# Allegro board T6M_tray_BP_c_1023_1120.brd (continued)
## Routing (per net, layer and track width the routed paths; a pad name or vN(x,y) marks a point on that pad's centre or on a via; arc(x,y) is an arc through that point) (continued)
ENET1G_3_MDI1N: length 33.3
  IN2 w0.152: J7.F2 347.53,8.64 347.67,8.5 348.18,8.5 348.43,8.76 348.43,19.85 346.93,21.35 346.93,27.7 346.4,28.23 346.4,30.22 347.48,31.3 347.48,33.37 345.98,34.87 344.8,34.87 343.69,35.98 J23.A6
ENET1G_3_MDI1P: length 33.7
  IN2 w0.152: J23.A3 346.45,38.51 346.45,34.98 347.89,33.54 347.89,31.13 346.81,30.05 346.81,28.4 347.34,27.86 347.34,21.51 348.84,20.02 348.84,8.59 348.35,8.1 347.67,8.1 347.53,7.96 J7.E2
ENET1G_3_MDI2N: length 41.8
  BOTTOM w0.147: J7.C2 347.53,4.4 347.38,4.25 346.84,4.25 346.69,4.4 346.69,14.68 350.46,18.46 350.46,21.58 350.62,21.74 350.62,22.18 350.46,22.34 350.46,22.78 350.62,22.94 350.62,23.38 350.46,23.54 350.46,23.98 350.62,24.14 350.62,24.58 350.46,24.74 350.46,25.18 350.62,25.34 350.62,25.78 350.46,25.94 350.46,32.51 348.58,34.39 347.5,34.39 346.61,35.28 346.61,36.8 345.81,37.61 344.82,37.61 344.73,37.52 344.6,37.45 344.4,37.52 J23.A5
ENET1G_3_MDI2P: length 41.1
  BOTTOM w0.147: J23.A4 344.67,36.98 344.74,37.18 344.91,37.27 344.95,37.3 345.68,37.3 346.3,36.68 346.3,35.15 347.37,34.09 348.46,34.09 350.16,32.38 350.16,18.59 346.38,14.81 346.38,4.27 346.71,3.95 347.36,3.95 347.53,3.78 J7.B2
ENET1G_3_MDI3N: length 55.1
  IN1 w0.152: J7.B3 345.53,3.16 345.37,3 345.03,3 344.73,3.3 344.73,14.33 346.71,16.31 346.71,25.66 350.67,29.62 350.67,33.71 350.41,33.96 350.41,39.42 349.65,40.18 340.79,40.18 339.78,39.17 339.78,37.7 340.32,37.16 340.45,37.16 340.5,37.14 340.57,36.93 J23.A8
ENET1G_3_MDI3P: length 54.4
  IN1 w0.152: J7.A3 345.53,2.46 345.39,2.6 344.86,2.6 344.32,3.13 344.32,14.49 346.3,16.48 346.3,17.89 346.15,18.04 346.15,18.5 346.3,18.65 346.3,19.11 346.15,19.26 346.15,19.71 346.3,19.87 346.3,20.32 346.15,20.48 346.15,20.93 346.3,21.09 346.3,21.54 346.15,21.7 346.15,22.15 346.3,22.31 346.3,25.83 350.26,29.79 350.26,33.54 350.01,33.79 350.01,39.25 349.48,39.78 340.96,39.78 340.18,39 340.18,37.87 340.49,37.57 340.54,37.57 340.68,37.5 340.68,37.5 340.88,37.57 J23.A7
ENET1G_4_MDI0N: length 33.3
  IN2 w0.152: J7.C4 343.53,4.44 343.66,4.3 344.18,4.3 344.33,4.46 344.33,15.34 341.5,18.17 341.5,24.28 338.5,27.28 338.5,30.2 339.39,31.09 340.42,31.09 340.54,30.97 340.68,30.9 340.88,30.97 J23.B2
ENET1G_4_MDI0P: length 33.1
  IN2 w0.152: J23.B1 340.57,30.33 340.5,30.54 340.3,30.63 340.26,30.68 339.55,30.68 338.91,30.03 338.91,27.45 341.91,24.45 341.91,18.34 344.74,15.51 344.74,4.29 344.35,3.9 343.66,3.9 343.53,3.77 J7.B4
ENET1G_4_MDI1N: length 35.7
  IN1 w0.152: J7.B5 341.53,3.17 341.69,3 342.07,3 342.26,3.19 342.26,18.8 343.43,19.96 343.43,26.57 341.04,28.96 341.04,30.02 341.8,30.78 345.31,30.78 J23.B6
ENET1G_4_MDI1P: length 35
  IN1 w0.152: J7.A5 341.53,2.4 341.73,2.6 342.24,2.6 342.67,3.02 342.67,18.63 343.83,19.8 343.83,26.74 341.45,29.12 341.45,29.85 341.97,30.38 343.89,30.38 344.09,30.18 344.09,29.64 343.83,29.38 J23.B3
ENET1G_4_MDI2N: length 29.3
  BOTTOM w0.147: J23.B5 344.67,30.38 344.74,30.58 344.91,30.67 345,30.76 345.67,30.76 346.1,30.33 346.1,27.2 345.72,26.83 345.49,26.83 345.18,26.51 345.18,26.28 344.87,25.97 344.64,25.97 344.33,25.66 344.33,25.43 344.02,25.12 343.79,25.12 343.47,24.81 343.47,24.58 342.49,23.59 342.49,7.42 342.23,7.15 341.63,7.15 341.53,7.25 J7.E5
ENET1G_4_MDI2P: length 30
  BOTTOM w0.147: J7.D5 341.53,6.72 341.66,6.85 342.35,6.85 342.79,7.29 342.79,23.46 346.41,27.08 346.41,30.45 345.8,31.06 344.88,31.06 344.73,30.92 344.6,30.85 344.4,30.92 J23.B4
ENET1G_4_MDI3N: length 44.4
  IN1 w0.152: J23.B8 348.5,30.97 348.3,30.9 348.16,30.97 347.9,31.23 347.9,32.79 346.68,34.01 340.71,34.01 338.65,31.95 338.65,27.59 341.6,24.64 341.6,20.97 340.33,19.7 340.33,4.64 339.99,4.3 339.69,4.3 339.53,4.47 J7.C6
ENET1G_4_MDI3P: length 44.2
  IN1 w0.152: J23.B7 348.19,30.33 348.12,30.54 347.92,30.63 347.49,31.06 347.49,32.62 346.51,33.6 340.88,33.6 339.06,31.78 339.06,27.76 342.01,24.81 342.01,20.8 340.74,19.53 340.74,4.47 340.16,3.9 339.69,3.9 339.53,3.73 J7.B6
ENET10G_1_LOS: length 13.5
  TOP w0.29: U5.8 v1(140.29,19.94) ; R13.2 130.5,22.78 130.55,22.73 R67.1 v1(131.19,22.21)
  IN2 w0.183: v1(140.29,19.94) 139.96,19.61 138.02,19.61 136.12,21.51 131.89,21.51 v1(131.19,22.21)
ENET10G_1_MOD_DEF0: length 18
  TOP w0.29: R66.1 131.02,21.14 132.19,22.31 v1(132.19,23.11) 130.96,24.35 R9.2 ; U5.6 v1(141.89,20.12)
  IN2 w0.183: v1(141.89,20.12) 141.12,20.12 140.79,20.45 139.04,20.45 135.97,23.52 134.16,23.52 133.76,23.11 v1(132.19,23.11)
ENET10G_1_RDN: length 20
  TOP w0.244: v1(132.92,5.23) 133.1,5.04 arc(133.27,4.93) 133.46,4.89 133.74,4.89 arc(133.93,4.93) 134.1,5.04 134.14,5.08 arc(134.31,5.19) 134.5,5.23 134.76,5.23 arc(134.89,5.21) 134.99,5.14 135.09,5.04 arc(135.26,4.93) 135.45,4.89 135.68,4.89 arc(135.87,4.93) 136.04,5.04 136.08,5.08 arc(136.25,5.19) 136.44,5.23 136.68,5.23 arc(136.81,5.21) 136.92,5.14 137.01,5.04 arc(137.18,4.93) 137.37,4.89 137.75,4.89 arc(137.95,4.93) 138.11,5.04 138.15,5.08 arc(138.32,5.19) 138.51,5.23 138.72,5.23 arc(138.87,5.2) 139,5.12 139.12,5 arc(139.24,4.92) 139.38,4.89 139.53,4.89 arc(139.62,4.91) 139.7,4.96 139.92,5.18 arc(139.97,5.26) 139.99,5.35 139.99,5.79 arc(139.95,5.98) 139.84,6.15 139.81,6.18 arc(139.7,6.35) 139.66,6.54 139.66,6.8 arc(139.7,6.99) 139.81,7.16 139.99,7.34 139.99,8.85 139.89,8.95 139.89,8.95 U5.12
  BOTTOM w0.244: J24.E1 128.93,7.3 129.33,7.3 arc(129.64,7.24) 129.9,7.06 arc(130.08,6.8) 130.14,6.49 130.14,5.23 arc(130.17,5.1) 130.24,4.99 arc(130.35,4.92) 130.48,4.89 arc(130.61,4.92) 130.72,4.99 130.81,5.08 arc(130.97,5.19) 131.15,5.22 131.35,5.22 arc(131.54,5.18) 131.71,5.07 131.74,5.04 arc(131.9,4.93) 132.1,4.89 132.37,4.89 arc(132.57,4.93) 132.73,5.04 v1(132.92,5.23)
ENET10G_1_RDP: length 20
  TOP w0.244: v1(132.92,3.96) 133.25,4.29 139.67,4.29 arc(139.86,4.33) 140.03,4.44 140.44,4.86 arc(140.55,5.02) 140.59,5.21 140.59,8.85 140.69,8.95 U5.13
  BOTTOM w0.244: v1(132.92,3.96) 132.58,4.29 130.48,4.29 arc(130.12,4.36) 129.81,4.57 arc(129.61,4.87) 129.54,5.23 129.54,6.49 arc(129.52,6.57) 129.48,6.64 arc(129.41,6.68) 129.33,6.7 128.93,6.7 J24.D1
ENET10G_1_RS0: length 21.2
  TOP w0.29: R11.2 v1(156.34,25.44) R42.2 ; v1(143.21,22.28) 141.09,20.16 U5.7
  IN2 w0.183: v1(143.21,22.28) 146.3,22.28 147.57,23.55 150.77,23.55 152.67,25.44 v1(156.34,25.44)
ENET10G_1_RS1: length 24.8
  TOP w0.29: R15.2 v1(156.34,26.71) R43.2 ; U5.9 v1(139.49,22.71)
  IN2 w0.183: v1(139.49,22.71) 140.49,22.71 140.67,22.89 146.05,22.89 147.24,24.08 150.55,24.08 153.18,26.71 v1(156.34,26.71)
ENET10G_1_SCL: length 36.2
  TOP w0.29: v1(131.93,24.49) 130.97,25.44 R7.2 ; U5.5 v1(142.69,20.52)
  IN1 w0.183: v1(131.93,24.49) 131.8,24.49 127.64,20.32 127.64,16.55 125.22,14.14 125.22,8.39 J24.E3
  IN2 w0.183: v1(131.93,24.49) 132.23,24.18 136.27,24.18 139.3,21.15 142.07,21.15 v1(142.69,20.52)
ENET10G_1_SDA: length 41.7
  TOP w0.29: v1(133.53,25.22) 132.22,26.53 R5.2 ; U5.4 v1(143.49,20.8)
  IN1 w0.183: v1(133.53,25.22) 133.53,24.87 132.38,23.72 132.03,23.72 128.32,20.02 128.32,16.1 127.58,15.37 127.58,7.39 127.08,6.88 125.11,6.88 J24.D3
  IN2 w0.183: v1(143.49,20.8) 142.27,22.02 139.38,22.02 136.18,25.22 v1(133.53,25.22)
ENET10G_1_TDN: length 25.6
  TOP w0.244: U5.19 145.49,8.95 145.39,8.85 145.39,6.05 v1(145.73,5.71)
  BOTTOM w0.244: v1(145.73,5.71) 145.39,6.05 145.39,6.72 arc(145.35,6.92) 145.24,7.08 144.98,7.34 arc(144.81,7.45) 144.62,7.49 143.98,7.49 arc(143.56,7.41) 143.2,7.17 142.76,6.73 arc(142.6,6.62) 142.4,6.58 135.63,6.58 arc(135.53,6.6) 135.45,6.65 130.93,11.18 arc(130.57,11.42) 130.14,11.5 128.93,11.5 J24.H1
ENET10G_1_TDP: length 25.6
  TOP w0.244: v1(144.46,5.71) 144.79,6.05 144.79,8.85 144.69,8.95 U5.18
  BOTTOM w0.244: v1(144.46,5.71) 144.79,6.05 144.79,6.58 arc(144.77,6.68) 144.72,6.76 144.65,6.82 arc(144.57,6.88) 144.48,6.89 143.98,6.89 arc(143.79,6.85) 143.63,6.74 143.18,6.3 arc(142.82,6.06) 142.4,5.98 141.98,5.98 arc(141.82,5.95) 141.68,5.87 arc(141.67,5.86) 141.66,5.85 arc(141.51,5.75) 141.34,5.71 140.95,5.71 arc(140.78,5.75) 140.63,5.85 arc(140.62,5.86) 140.61,5.87 arc(140.48,5.95) 140.32,5.98 139.87,5.98 arc(139.71,5.95) 139.57,5.87 arc(139.56,5.86) 139.55,5.85 arc(139.41,5.75) 139.23,5.71 138.85,5.71 arc(138.67,5.75) 138.53,5.85 arc(138.52,5.86) 138.51,5.87 arc(138.37,5.95) 138.21,5.98 137.79,5.98 arc(137.63,5.95) 137.49,5.87 arc(137.48,5.86) 137.47,5.85 arc(137.32,5.75) 137.15,5.71 136.79,5.71 arc(136.62,5.75) 136.47,5.85 arc(136.47,5.85) 136.46,5.85 136.45,5.87 arc(136.31,5.95) 136.15,5.98 135.49,5.98 arc(135.29,6.02) 135.13,6.13 134.95,6.31 arc(134.78,6.42) 134.59,6.45 134.55,6.45 arc(134.36,6.49) 134.19,6.6 133.97,6.82 arc(133.86,6.99) 133.83,7.18 133.83,7.22 arc(133.79,7.41) 133.68,7.58 133.46,7.8 arc(133.29,7.91) 133.1,7.95 133.04,7.95 arc(132.84,7.98) 132.68,8.09 132.48,8.29 arc(132.37,8.45) 132.33,8.65 132.33,8.71 arc(132.3,8.9) 132.19,9.07 131.97,9.29 arc(131.8,9.4) 131.61,9.44 131.6,9.44 arc(131.4,9.48) 131.24,9.59 130.99,9.83 arc(130.88,10) 130.84,10.19 130.84,10.2 arc(130.8,10.4) 130.69,10.56 130.5,10.75 arc(130.34,10.86) 130.14,10.9 128.93,10.9 J24.G1
ENET10G_1_TX_DIS: length 17.8
  TOP w0.29: U5.3 v1(144.29,20.7) ; R3.2 v1(156.36,24.17) R41.2
  IN2 w0.183: v1(156.36,24.17) 154.16,24.17 151.45,21.46 145.05,21.46 v1(144.29,20.7)
ENET10G_1_TX_FAULT: length 16
  TOP w0.29: U5.2 v1(145.09,20.24) ; R1.2 v1(156.18,22.9) R40.2
  IN2 w0.183: v1(145.09,20.24) 145.8,20.95 151.66,20.95 153.61,22.9 v1(156.18,22.9)
ENET10G_2_LOS: length 26.2
  TOP w0.29: v1(114.81,25.96) 114.81,25.98 115.37,26.55 R14.2 ; R68.1 v1(118.41,22.24) ; U6.8 v1(102.37,22.74)
  IN2 w0.183: v1(118.41,22.24) 115.57,25.08 115.57,25.2 v1(114.81,25.96) 114.25,25.96 112.48,24.19 103.81,24.19 v1(102.37,22.74)
ENET10G_2_MOD_DEF0: length 24
  TOP w0.29: R69.1 v1(118.39,21.15) ; v1(114.83,24.64) 115.65,25.45 R10.2 ; U6.6 v1(103.97,22.5)
  IN2 w0.183: v1(118.39,21.15) 118.39,21.41 115.16,24.64 v1(114.83,24.64) 113.67,24.64 112.73,23.7 105.16,23.7 v1(103.97,22.5)
ENET10G_2_RDN: length 23.8
  TOP w0.244: v1(101.73,5.58) 102.07,5.91 102.07,8.85 101.97,8.95 U6.12
  BOTTOM w0.244: J24.F6 118.13,8.6 117.58,8.6 arc(117.16,8.52) 116.8,8.28 115.71,7.18 arc(115.63,7.13) 115.54,7.11 104.32,7.11 arc(104.13,7.15) 103.97,7.26 103.91,7.32 arc(103.74,7.43) 103.55,7.47 102.88,7.47 arc(102.68,7.43) 102.52,7.32 102.14,6.94 arc(102.03,6.78) 101.99,6.58 101.99,5.84 v1(101.73,5.58)
ENET10G_2_RDP: length 23.8
  TOP w0.244: v1(103,5.58) 102.67,5.91 102.67,8.85 102.77,8.95 U6.13
  BOTTOM w0.244: J24.E6 118.13,8 117.58,8 arc(117.39,7.96) 117.22,7.85 116.03,6.66 arc(115.87,6.55) 115.67,6.51 114.57,6.51 arc(114.38,6.47) 114.21,6.36 114.19,6.35 arc(114.03,6.24) 113.84,6.2 113.4,6.2 arc(113.29,6.22) 113.2,6.28 113.12,6.36 arc(112.95,6.47) 112.76,6.51 112.49,6.51 arc(112.3,6.47) 112.14,6.36 112.12,6.35 arc(111.95,6.24) 111.76,6.2 111.34,6.2 arc(111.24,6.22) 111.14,6.28 111.06,6.36 arc(110.9,6.47) 110.7,6.51 110.45,6.51 arc(110.26,6.47) 110.09,6.36 110.08,6.35 arc(109.91,6.24) 109.72,6.2 109.24,6.2 arc(109.13,6.22) 109.04,6.28 108.95,6.36 arc(108.79,6.47) 108.59,6.51 108.41,6.51 arc(108.22,6.47) 108.05,6.36 108.03,6.35 arc(107.87,6.24) 107.67,6.2 107.25,6.2 arc(107.15,6.22) 107.05,6.28 106.97,6.36 arc(106.81,6.47) 106.61,6.51 106.37,6.51 arc(106.17,6.47) 106.01,6.36 arc(105.85,6.26) 105.67,6.22 105.2,6.22 arc(105.11,6.24) 105.03,6.29 104.96,6.36 arc(104.8,6.47) 104.61,6.51 104.32,6.51 arc(103.9,6.6) 103.54,6.84 103.51,6.87 103.02,6.87 arc(102.92,6.85) 102.84,6.8 102.66,6.62 arc(102.61,6.54) 102.59,6.45 102.59,5.99 v1(103,5.58)
ENET10G_2_RS0: length 19.5
  TOP w0.29: U6.7 v1(103.17,20.9) ; R44.2 v1(90.83,27.57) R12.2
  IN2 w0.183: v1(90.83,27.57) 94.83,27.57 101.5,20.9 v1(103.17,20.9)
ENET10G_2_RS1: length 17
  TOP w0.29: R16.2 v1(90.64,26.15) R45.2 ; U6.9 v1(101.57,20.15)
  IN2 w0.183: v1(90.64,26.15) 95.56,26.15 v1(101.57,20.15)
ENET10G_2_SCL: length 35.1
  TOP w0.29: U6.5 v1(104.77,20.55) ; v1(115.29,23.44) 116.21,24.36 R8.2
  IN2 w0.183: v1(104.77,20.55) 104.77,20.8 105.84,21.87 109.51,21.87 109.92,21.46 112.85,21.46 114.83,23.44 v1(115.29,23.44) 117.17,21.56 117.17,12.04 118.11,11.1 118.97,11.1 119.2,10.87 119.21,10.87 120.3,9.78 121.75,9.78 J24.F4
ENET10G_2_SDA: length 33.8
  TOP w0.29: v1(115.14,22.05) 116.36,23.27 R6.2 ; U6.4 v1(105.57,20.5)
  IN2 w0.183: v1(105.57,20.5) 106.1,21.03 109.42,21.03 109.86,20.6 113.08,20.6 114.53,22.05 v1(115.14,22.05) 116.31,20.88 116.31,11.46 118.06,9.7 118.92,9.7 120.24,8.38 121.75,8.38 J24.E4
ENET10G_2_TDN: length 24.3
  TOP w0.244: v1(113.76,9.19) 114.17,8.78 114.17,8.06 arc(114.13,7.86) 114.02,7.7 113.97,7.64 arc(113.86,7.48) 113.82,7.28 113.82,7.02 arc(113.86,6.82) 113.97,6.66 114.02,6.6 arc(114.13,6.44) 114.17,6.24 114.17,5.52 arc(114.15,5.43) 114.1,5.35 113.95,5.19 arc(113.87,5.14) 113.77,5.12 112.72,5.12 arc(112.52,5.16) 112.36,5.27 112.3,5.33 arc(112.14,5.44) 111.94,5.48 111.63,5.48 arc(111.44,5.44) 111.27,5.33 111.21,5.27 arc(111.05,5.16) 110.85,5.12 110.56,5.12 arc(110.36,5.16) 110.2,5.27 110.14,5.33 arc(109.98,5.44) 109.78,5.48 109.45,5.48 arc(109.25,5.44) 109.09,5.33 109.03,5.27 arc(108.86,5.16) 108.67,5.12 108.2,5.12 arc(108,5.16) 107.84,5.27 107.62,5.49 arc(107.51,5.65) 107.47,5.85 107.47,8.85 107.57,8.95 U6.19
  BOTTOM w0.244: J24.I6 118.13,12.8 117.59,12.8 arc(117.39,12.84) 117.23,12.95 117.13,13.04 arc(117.03,13.11) 116.91,13.13 116.47,13.13 arc(116.27,13.09) 116.11,12.98 116.07,12.95 arc(115.91,12.84) 115.71,12.8 115.51,12.8 arc(115.09,12.72) 114.73,12.48 114.5,12.25 arc(114.26,11.89) 114.17,11.46 114.17,11.31 arc(114.14,11.16) 114.06,11.04 114.03,11.01 arc(113.93,10.86) 113.89,10.67 113.89,10.4 arc(113.93,10.2) 114.04,10.04 114.07,10.01 arc(114.14,9.9) 114.17,9.78 114.17,9.61 v1(113.76,9.19)
ENET10G_2_TDP: length 24.3
  TOP w0.244: v1(115.18,9.19) 114.77,8.78 114.77,5.38 arc(114.73,5.19) 114.62,5.02 114.27,4.67 arc(114.11,4.56) 113.91,4.52 108.2,4.52 arc(107.77,4.61) 107.41,4.85 107.19,5.06 arc(106.95,5.42) 106.87,5.85 106.87,8.85 106.77,8.95 U6.18
  BOTTOM w0.244: J24.H6 118.13,12.2 115.51,12.2 arc(115.31,12.16) 115.15,12.05 114.92,11.82 arc(114.81,11.66) 114.77,11.46 114.77,9.61 v1(115.18,9.19)
ENET10G_2_TX_DIS: length 23.2
  TOP w0.29: v1(104.72,21.74) 105.38,21.74 106.37,20.75 U6.3 ; R47.2 v1(90.88,29.12) R4.2
  IN2 w0.183: v1(90.88,29.12) 93.97,29.12 101.35,21.74 v1(104.72,21.74)
ENET10G_2_TX_FAULT: length 13.2
  TOP w0.29: R2.2 R46.2 114.99,21.09 v1(114.58,20.68) ; U6.2 v1(107.17,19.91)
  IN2 w0.183: v1(114.58,20.68) 113.84,19.94 109.42,19.94 109.05,20.31 107.31,20.31 107.17,20.17 v1(107.17,19.91)
ENET10G_3_LOS: length 13.2
  TOP w0.29: R29.2 R70.1 v1(352.4,22.16) ; U7.8 v1(361.29,19.91)
  IN2 w0.183: v1(352.4,22.16) 353.12,21.44 358.62,21.44 359.67,20.39 360.08,20.39 360.55,19.91 v1(361.29,19.91)
ENET10G_3_MOD_DEF0: length 18.1
  TOP w0.29: R25.2 351.81,24.15 352.64,24.15 v1(353.31,23.47) 353.31,22.2 352.21,21.09 R75.1 ; U7.6 v1(362.89,20.07)
  IN2 w0.183: v1(362.89,20.07) 362.23,20.07 361.24,21.06 359.77,21.06 357.36,23.47 v1(353.31,23.47)
ENET10G_3_RDN: length 20
  TOP w0.244: U7.12 360.89,8.95 360.89,8.95 360.99,8.85 360.99,7.34 360.81,7.16 arc(360.7,6.99) 360.66,6.8 360.66,6.54 arc(360.7,6.35) 360.81,6.18 360.84,6.15 arc(360.95,5.98) 360.99,5.79 360.99,5.35 arc(360.97,5.26) 360.92,5.18 360.7,4.96 arc(360.62,4.91) 360.53,4.89 360.38,4.89 arc(360.24,4.92) 360.12,5 360,5.12 arc(359.87,5.2) 359.72,5.23 359.51,5.23 arc(359.32,5.19) 359.15,5.08 359.11,5.04 arc(358.95,4.93) 358.75,4.89 358.37,4.89 arc(358.18,4.93) 358.01,5.04 357.92,5.14 arc(357.81,5.21) 357.68,5.23 357.44,5.23 arc(357.25,5.19) 357.08,5.08 357.04,5.04 arc(356.87,4.93) 356.68,4.89 356.45,4.89 arc(356.26,4.93) 356.09,5.04 355.99,5.14 arc(355.89,5.21) 355.76,5.23 355.5,5.23 arc(355.31,5.19) 355.14,5.08 355.1,5.04 arc(354.93,4.93) 354.74,4.89 354.46,4.89 arc(354.27,4.93) 354.1,5.04 v1(353.92,5.23)
  BOTTOM w0.244: J7.E1 349.93,7.3 350.33,7.3 arc(350.64,7.24) 350.9,7.06 arc(351.08,6.8) 351.14,6.49 351.14,5.23 arc(351.17,5.1) 351.24,4.99 arc(351.35,4.92) 351.48,4.89 arc(351.61,4.92) 351.72,4.99 351.81,5.08 arc(351.97,5.19) 352.15,5.22 352.35,5.22 arc(352.54,5.18) 352.71,5.07 352.74,5.04 arc(352.9,4.93) 353.1,4.89 353.37,4.89 arc(353.57,4.93) 353.73,5.04 v1(353.92,5.23)
ENET10G_3_RDP: length 20
  TOP w0.244: v1(353.92,3.96) 354.25,4.29 360.67,4.29 arc(360.86,4.33) 361.03,4.44 361.44,4.86 arc(361.55,5.02) 361.59,5.21 361.59,8.85 361.69,8.95 U7.13
  BOTTOM w0.244: v1(353.92,3.96) 353.58,4.29 351.48,4.29 arc(351.12,4.36) 350.81,4.57 arc(350.61,4.87) 350.54,5.23 350.54,6.49 arc(350.52,6.57) 350.48,6.64 arc(350.41,6.68) 350.33,6.7 349.93,6.7 J7.D1
ENET10G_3_RS0: length 21.1
  TOP w0.29: v1(364.29,22.38) 362.09,20.18 U7.7 ; R27.2 v1(377.16,26.23) R48.2
  IN2 w0.183: v1(377.16,26.23) 375.32,26.23 373.05,23.95 368.35,23.95 366.78,22.38 v1(364.29,22.38)
ENET10G_3_RS1: length 23.2
  TOP w0.29: v1(363.07,22.48) 363.02,22.48 360.49,19.95 U7.9 ; R49.2 v1(377.14,27.78) R31.2
  IN2 w0.183: v1(363.07,22.48) 363.55,22.96 366.55,22.96 371.36,27.78 v1(377.14,27.78)
ENET10G_3_SCL: length 36.4
  TOP w0.29: U7.5 v1(363.69,20.37) ; v1(353.03,24.79) 352.38,25.44 R23.2
  IN1 w0.183: v1(353.03,24.79) 352.86,24.79 348.08,20.02 348.08,15.77 346.23,13.92 346.23,8.4 J7.E3
  IN2 w0.183: v1(353.03,24.79) 353.62,24.21 357.53,24.21 359.99,21.74 361.85,21.74 362.48,21.11 362.95,21.11 v1(363.69,20.37)
ENET10G_3_SDA: length 41.4
  TOP w0.29: v1(354.38,25.27) 353.12,26.53 R21.2 ; U7.4 v1(364.49,20.75)
  IN1 w0.183: J7.D3 346.14,6.91 347.93,6.91 348.56,7.54 348.56,14.35 348.73,14.52 348.73,19.62 353.16,24.05 353.52,24.05 354.38,24.92 v1(354.38,25.27)
  IN2 w0.183: v1(354.38,25.27) 354.79,24.87 357.78,24.87 360.22,22.43 362.1,22.43 362.72,21.81 363.43,21.81 v1(364.49,20.75)
ENET10G_3_TDN: length 25.6
  TOP w0.244: v1(366.73,5.71) 366.39,6.05 366.39,8.85 366.49,8.95 U7.19
  BOTTOM w0.244: J7.H1 349.93,11.5 351.14,11.5 arc(351.57,11.42) 351.93,11.18 356.45,6.65 arc(356.53,6.6) 356.63,6.58 363.4,6.58 arc(363.6,6.62) 363.76,6.73 364.2,7.17 arc(364.56,7.41) 364.98,7.49 365.62,7.49 arc(365.81,7.45) 365.98,7.34 366.24,7.08 arc(366.35,6.92) 366.39,6.72 366.39,6.05 v1(366.73,5.71)
ENET10G_3_TDP: length 25.6
  TOP w0.244: v1(365.46,5.71) 365.79,6.05 365.79,8.85 365.69,8.95 U7.18
  BOTTOM w0.244: v1(365.46,5.71) 365.79,6.05 365.79,6.58 arc(365.77,6.68) 365.72,6.76 365.65,6.82 arc(365.57,6.88) 365.48,6.89 364.98,6.89 arc(364.79,6.85) 364.63,6.74 364.18,6.3 arc(363.82,6.06) 363.4,5.98 362.98,5.98 arc(362.82,5.95) 362.68,5.87 arc(362.67,5.86) 362.66,5.85 arc(362.51,5.75) 362.34,5.71 361.95,5.71 arc(361.78,5.75) 361.63,5.85 arc(361.63,5.86) 361.61,5.87 arc(361.48,5.95) 361.32,5.98 360.87,5.98 arc(360.71,5.95) 360.57,5.87 arc(360.56,5.86) 360.55,5.85 arc(360.41,5.75) 360.23,5.71 359.85,5.71 arc(359.67,5.75) 359.53,5.85 arc(359.52,5.86) 359.51,5.87 arc(359.37,5.95) 359.21,5.98 358.79,5.98 arc(358.63,5.95) 358.49,5.87 arc(358.48,5.86) 358.47,5.85 arc(358.32,5.75) 358.15,5.71 357.79,5.71 arc(357.62,5.75) 357.47,5.85 arc(357.47,5.85) 357.46,5.85 357.45,5.87 arc(357.31,5.95) 357.15,5.98 356.49,5.98 arc(356.29,6.02) 356.13,6.13 355.95,6.31 arc(355.78,6.42) 355.59,6.45 355.55,6.45 arc(355.36,6.49) 355.19,6.6 354.97,6.82 arc(354.86,6.99) 354.83,7.18 354.83,7.22 arc(354.79,7.41) 354.68,7.58 354.46,7.8 arc(354.29,7.91) 354.1,7.95 354.04,7.95 arc(353.84,7.98) 353.68,8.09 353.48,8.29 arc(353.37,8.45) 353.33,8.65 353.33,8.71 arc(353.3,8.9) 353.19,9.07 352.97,9.29 arc(352.8,9.4) 352.61,9.44 352.6,9.44 arc(352.4,9.48) 352.24,9.59 351.99,9.83 arc(351.88,10) 351.84,10.19 351.84,10.2 arc(351.8,10.4) 351.69,10.56 351.5,10.75 arc(351.34,10.86) 351.14,10.9 349.93,10.9 J7.G1
ENET10G_3_TX_DIS: length 17.6
  TOP w0.29: U7.3 v1(365.29,20.6) ; R51.2 v1(377.19,24.91) R19.2
  IN2 w0.183: v1(377.19,24.91) 374.92,24.91 371.5,21.49 366.18,21.49 v1(365.29,20.6)
ENET10G_3_TX_FAULT: length 15.9
  TOP w0.29: R17.2 v1(377.11,23.64) R50.2 ; U7.2 v1(366.09,20.09)
  IN2 w0.183: v1(366.09,20.09) 366.85,20.85 372.21,20.85 374.99,23.64 v1(377.11,23.64)
ENET10G_4_LOS: length 26.5
  TOP w0.29: v1(338.68,21.06) 338.68,21.06 R72.1 ; U8.8 v1(323.37,22.63) ; R30.2 v1(336.04,25.21)
  IN2 w0.183: v1(338.68,21.06) 338.71,21.08 338.71,21.64 336.04,24.31 v1(336.04,25.21) 335.04,25.21 333.93,24.1 326.24,24.1 324.76,22.63 v1(323.37,22.63)
ENET10G_4_MOD_DEF0: length 23.5
  TOP w0.29: U8.6 v1(324.97,22.15) ; v1(335.64,23.57) 336.1,24.04 R26.2 ; v1(337.69,20.68) 337.95,20.42 339.14,20.42 R73.1
  IN2 w0.183: v1(337.69,20.68) 337.69,21.51 v1(335.64,23.57) 326.39,23.57 v1(324.97,22.15)
ENET10G_4_RDN: length 23.8
  TOP w0.244: U8.12 322.97,8.95 323.07,8.85 323.07,5.91 v1(322.73,5.58)
  BOTTOM w0.244: v1(322.73,5.58) 322.99,5.84 322.99,6.58 arc(323.03,6.78) 323.14,6.94 323.52,7.32 arc(323.68,7.43) 323.88,7.47 324.55,7.47 arc(324.74,7.43) 324.91,7.32 324.97,7.26 arc(325.13,7.15) 325.32,7.11 336.54,7.11 arc(336.63,7.13) 336.71,7.18 337.8,8.28 arc(338.16,8.52) 338.58,8.6 339.13,8.6 J7.F6
ENET10G_4_RDP: length 23.8
  TOP w0.244: U8.13 323.77,8.95 323.67,8.85 323.67,5.91 v1(324,5.58)
  BOTTOM w0.244: J7.E6 339.13,8 338.58,8 arc(338.39,7.96) 338.22,7.85 337.03,6.66 arc(336.87,6.55) 336.67,6.51 335.57,6.51 arc(335.38,6.47) 335.21,6.36 335.19,6.35 arc(335.03,6.24) 334.84,6.2 334.4,6.2 arc(334.29,6.22) 334.2,6.28 334.12,6.36 arc(333.95,6.47) 333.76,6.51 333.49,6.51 arc(333.3,6.47) 333.14,6.36 333.12,6.35 arc(332.95,6.24) 332.76,6.2 332.34,6.2 arc(332.24,6.22) 332.14,6.28 332.06,6.36 arc(331.9,6.47) 331.7,6.51 331.45,6.51 arc(331.26,6.47) 331.09,6.36 331.08,6.35 arc(330.91,6.24) 330.72,6.2 330.24,6.2 arc(330.13,6.22) 330.04,6.28 329.95,6.36 arc(329.79,6.47) 329.59,6.51 329.41,6.51 arc(329.22,6.47) 329.05,6.36 329.03,6.35 arc(328.87,6.24) 328.67,6.2 328.25,6.2 arc(328.15,6.22) 328.05,6.28 327.97,6.36 arc(327.81,6.47) 327.61,6.51 327.37,6.51 arc(327.17,6.47) 327.01,6.36 arc(326.85,6.26) 326.67,6.22 326.2,6.22 arc(326.11,6.24) 326.03,6.29 325.96,6.36 arc(325.8,6.47) 325.61,6.51 325.32,6.51 arc(324.9,6.6) 324.54,6.84 324.51,6.87 324.02,6.87 arc(323.92,6.85) 323.84,6.8 323.66,6.62 arc(323.61,6.54) 323.59,6.45 323.59,5.99 v1(324,5.58)
ENET10G_4_RS0: length 19.1
  TOP w0.29: U8.7 v1(324.17,20.07) ; R28.2 v1(311.66,27.52) R52.2
  IN2 w0.183: v1(324.17,20.07) 323.31,20.07 315.85,27.52 v1(311.66,27.52)
ENET10G_4_RS1: length 16.8
  TOP w0.29: R32.2 v1(311.68,26.13) R53.2 ; U8.9 v1(322.57,19.91)
  IN2 w0.183: v1(322.57,19.91) 321.91,20.57 316.36,26.13 v1(311.68,26.13)
ENET10G_4_SCL: length 34.1
  TOP w0.29: v1(335.92,22.3) 336.56,22.95 R24.2 ; U8.5 v1(325.77,21.77)
  IN2 w0.183: J7.F4 342.75,9.78 341.3,9.78 339.97,11.1 339.04,11.1 336.55,13.59 336.55,21.67 v1(335.92,22.3) 334.56,22.3 333.75,21.49 331.47,21.49 330.86,22.1 326.1,22.1 v1(325.77,21.77)
ENET10G_4_SDA: length 33.2
  TOP w0.29: v1(335.66,20.98) 336.32,20.98 337.14,21.8 R22.2 ; U8.4 v1(326.57,21.41)
  IN2 w0.183: v1(326.57,21.41) 330.5,21.41 331.09,20.83 334.47,20.83 334.62,20.98 v1(335.66,20.98) 335.66,12.75 338.73,9.68 339.87,9.68 340.23,9.32 340.23,8.97 340.81,8.38 342.75,8.38 J7.E4
ENET10G_4_TDN: length 24.3
  TOP w0.244: v1(334.76,9.19) 335.17,8.78 335.17,8.06 arc(335.13,7.86) 335.02,7.7 334.97,7.64 arc(334.86,7.48) 334.82,7.28 334.82,7.02 arc(334.86,6.82) 334.97,6.66 335.02,6.6 arc(335.13,6.44) 335.17,6.24 335.17,5.52 arc(335.15,5.43) 335.1,5.35 334.95,5.19 arc(334.87,5.14) 334.77,5.12 333.72,5.12 arc(333.52,5.16) 333.36,5.27 333.3,5.33 arc(333.14,5.44) 332.94,5.48 332.63,5.48 arc(332.44,5.44) 332.27,5.33 332.21,5.27 arc(332.05,5.16) 331.85,5.12 331.56,5.12 arc(331.36,5.16) 331.2,5.27 331.14,5.33 arc(330.98,5.44) 330.78,5.48 330.45,5.48 arc(330.25,5.44) 330.09,5.33 330.03,5.27 arc(329.86,5.16) 329.67,5.12 329.2,5.12 arc(329,5.16) 328.84,5.27 328.62,5.49 arc(328.51,5.65) 328.47,5.85 328.47,8.85 328.57,8.95 U8.19
  BOTTOM w0.244: v1(334.76,9.19) 335.17,9.61 335.17,9.78 arc(335.14,9.9) 335.07,10.01 335.04,10.04 arc(334.93,10.2) 334.89,10.4 334.89,10.67 arc(334.93,10.86) 335.03,11.01 335.06,11.04 arc(335.14,11.16) 335.17,11.31 335.17,11.46 arc(335.26,11.89) 335.5,12.25 335.73,12.48 arc(336.09,12.72) 336.51,12.8 336.71,12.8 arc(336.91,12.84) 337.07,12.95 337.11,12.98 arc(337.27,13.09) 337.47,13.13 337.91,13.13 arc(338.03,13.11) 338.13,13.04 338.23,12.95 arc(338.39,12.84) 338.59,12.8 339.13,12.8 J7.I6
ENET10G_4_TDP: length 24.3
  TOP w0.244: v1(336.18,9.19) 335.77,8.78 335.77,5.38 arc(335.73,5.19) 335.62,5.02 335.27,4.67 arc(335.11,4.56) 334.91,4.52 329.2,4.52 arc(328.77,4.61) 328.41,4.85 328.19,5.06 arc(327.95,5.42) 327.87,5.85 327.87,8.85 327.77,8.95 U8.18
  BOTTOM w0.244: J7.H6 339.13,12.2 336.51,12.2 arc(336.31,12.16) 336.15,12.05 335.92,11.82 arc(335.81,11.66) 335.77,11.46 335.77,9.61 v1(336.18,9.19)
ENET10G_4_TX_DIS: length 22.9
  TOP w0.29: U8.3 v1(327.37,19.91) ; R55.2 v1(311.63,28.97) R20.2
  IN2 w0.183: v1(327.37,19.91) 325.6,19.91 324.26,21.26 322.81,21.26 315.1,28.97 v1(311.63,28.97)
ENET10G_4_TX_FAULT: length 24.5
  TOP w0.29: R18.2 v1(311.63,30.37) R54.2 ; U8.2 v1(328.17,20.37)
  IN2 w0.183: v1(311.63,30.37) 314.39,30.37 322.81,21.95 324.38,21.95 325.6,20.73 327.36,20.73 327.71,20.37 v1(328.17,20.37)
NODE1_EN: length 183.3
  TOP w0.29: J19.S3 6.03,44.26 10.33,39.96 11.66,39.96 14,37.63 16.59,37.63 23.05,31.17 28.69,31.17 v1(29.31,30.55)
  IN1 w0.183: JP4.1 5.21,23.72 14.94,23.72 21.76,30.55 v1(29.31,30.55)
  IN2 w0.183: J24.H2 125.83,12.5 125.83,21.16 125.76,21.23 125.76,24.92 123.23,27.44 123.23,29.93 124.36,31.06 124.36,32.44 122.17,34.62 118.36,34.62 117.63,35.36 113.54,35.36 112.29,34.11 110.79,34.11 109.45,35.46 87,35.46 82.09,30.55 v1(29.31,30.55)
NODE1_RXD: length 156.2
  TOP w0.29: J19.S2 7.3,43.83 10.57,40.56 11.9,40.56 14.24,38.22 16.84,38.22 23.28,31.78 v1(27.28,31.78)
  IN2 w0.183: J24.G3 125.3,11.27 125.3,20.94 125.22,21.01 125.22,24.7 122.69,27.22 122.69,30.14 123.85,31.29 123.85,32.21 121.97,34.09 118.8,34.09 116.2,31.5 112.72,31.5 109.72,34.5 86.91,34.5 82.47,30.06 28.99,30.06 v1(27.28,31.78)
NODE1_TXD: length 152.8
  TOP w0.29: J19.S1 8.57,43.42 10.84,41.15 12.15,41.15 14.49,38.81 17.08,38.81 23.52,32.38 v1(25.17,32.38) ; v1(124.16,18.72) 124.16,17.7 123.65,17.2 123.65,12.78 J24.H3
  IN2 w0.183: v1(124.16,18.72) 124.69,19.25 124.69,24.33 120.73,28.3 120.73,29.79 121.74,30.81 121.74,32.28 120.45,33.58 119.02,33.58 116.41,30.96 112.56,30.96 109.51,34.01 87.11,34.01 82.67,29.57 27.98,29.57 v1(25.17,32.38)
NODE2_EN: length 149.8
  TOP w0.29: v1(33.66,27.97) 33.66,29.09 32.83,29.92 29.01,29.92 28.36,30.57 22.8,30.57 16.42,36.96 13.61,36.96 11.2,39.37 8.94,39.37 4.76,43.55 J19.S4
  IN1 w0.183: v1(33.66,27.97) 32.09,26.41 JP3.1
  IN2 w0.183: v1(33.66,27.97) 83.13,27.97 87.71,32.54 108.92,32.54 119.1,22.36 119.1,14.83 119.84,14.1 119.84,11.19 J24.G5
NODE2_RXD: length 148.7
  TOP w0.29: J19.S6 2.22,43.93 10.44,35.71 15.98,35.71 22.31,29.38 v1(26.06,29.38)
  IN2 w0.183: v1(26.06,29.38) 26.95,28.49 82.97,28.49 87.52,33.04 109.11,33.04 120.02,22.13 120.02,14.86 121.26,13.61 121.26,11.67 J24.G4
NODE2_TXD: length 146.6
  TOP w0.29: J19.S5 3.49,43.58 8.46,38.61 10.83,38.61 13.08,36.36 16.17,36.36 22.56,29.98 27.63,29.98 28.52,29.09 v1(32.66,29.09)
  IN2 w0.183: J24.H4 121.82,12.51 121.82,13.87 120.57,15.11 120.57,22.26 109.31,33.53 87.32,33.53 82.87,29.09 v1(32.66,29.09)
NODE3_EN: length 418.5
  IN1 w0.183: JP8.1 3.71,21.5 3.71,23.88 4.29,24.46 5.69,24.46 5.92,24.23 14.66,24.23 21.54,31.11 27.33,31.11 27.79,31.57 27.79,33.2 28.22,33.63 v1(30.4,33.63)
  IN2 w0.183: v1(30.4,33.63) 81.03,33.63 86.64,39.24 110.42,39.24 113.59,42.41 131.65,42.41 134.9,39.16 203.19,39.16 206.42,35.93 318.09,35.93 322.04,31.98 331.78,31.98 335.25,35.46 337.36,35.46 338.63,34.19 343.66,34.19 345.51,32.33 345.51,31.22 344.23,29.93 344.23,28.47 345.69,27 345.69,20.8 346.83,19.66 346.83,12.5 J7.H2
  BOTTOM w0.29: v1(30.4,33.63) 23.37,33.63 18.57,38.43 13.13,38.43 11.76,39.8 9.45,39.8 6.03,43.22 J19.S10
NODE3_RXD: length 380.6
  IN2 w0.183: J7.G3 346.33,11.3 346.33,19.46 344.7,21.08 344.7,27.15 343.69,28.16 343.69,30.37 344.8,31.47 344.8,32.26 343.4,33.66 339.32,33.66 337.16,31.5 321.82,31.5 317.87,35.44 206.19,35.44 202.96,38.67 134.66,38.67 131.4,41.92 113.79,41.92 110.6,38.73 86.82,38.73 81.21,33.12 30.18,33.12 v1(29.03,34.26)
  BOTTOM w0.29: J19.S11 7.3,43.62 10.53,40.39 12.07,40.39 13.18,39.28 18.81,39.28 23.83,34.26 v1(29.03,34.26)
NODE3_TXD: length 377.2
  TOP w0.29: J7.H3 344.65,12.78 344.65,17.19 v1(344.98,17.53)
  IN2 w0.183: v1(27.66,34.87) 29.92,32.61 81.39,32.61 87,38.23 110.78,38.23 113.99,41.44 131.03,41.44 134.28,38.18 202.73,38.18 205.96,34.96 317.67,34.96 321.61,31.01 337.36,31.01 339.5,33.15 341.87,33.15 342.74,32.28 342.74,30.81 341.73,29.79 341.73,28.3 344.21,25.82 344.21,20.77 345.82,19.15 345.82,18.36 v1(344.98,17.53)
  BOTTOM w0.29: J19.S12 8.57,43.19 10.78,40.99 12.32,40.99 13.43,39.88 19.06,39.88 24.06,34.87 v1(27.66,34.87)
NODE4_EN: length 383.3
  IN1 w0.183: JP7.1 29.24,24.55 29.24,27.1 31.39,29.26 31.39,31.37 29.77,32.99 v1(28.32,32.99)
  IN2 w0.183: J7.G5 340.84,11.19 340.84,14.1 339.24,15.69 339.24,21.89 336.85,24.28 336.85,25.3 332.61,29.55 320.93,29.55 316.98,33.49 205.06,33.49 201.84,36.72 160.32,36.72 159.45,35.84 156.29,35.84 155.41,36.72 133.41,36.72 130.38,39.75 120.27,39.75 117.09,36.58 110.77,36.58 110.16,35.97 86.81,35.97 81.95,31.11 30.21,31.11 v1(28.32,32.99)
  BOTTOM w0.29: J19.S9 4.76,42.99 8.55,39.2 11.52,39.2 12.98,37.74 18.29,37.74 23.04,32.99 v1(28.32,32.99)
NODE4_RXD: length 374.5
  IN2 w0.183: J7.G4 342.26,11.67 342.26,13.61 339.75,16.12 339.75,22.15 337.54,24.36 337.54,25.32 332.83,30.03 321.13,30.03 317.18,33.98 205.33,33.98 202.11,37.21 160.12,37.21 159.26,36.35 156.49,36.35 155.63,37.21 133.68,37.21 130.64,40.24 119.87,40.24 116.71,37.08 87.24,37.08 81.75,31.6 v1(30.43,31.6)
  BOTTOM w0.29: J19.S7 2.22,43.68 9.73,36.17 11.02,36.17 11.38,36.53 17.56,36.53 22.44,31.65 23.87,31.65 24.36,31.17 27.61,31.17 28.04,31.6 v1(30.43,31.6)
NODE4_TXD: length 372.5
  IN2 w0.183: J7.H4 342.82,12.51 342.82,13.87 340.26,16.43 340.26,22.35 338.1,24.51 338.1,25.48 333.05,30.52 321.33,30.52 317.39,34.47 205.63,34.47 202.41,37.69 159.87,37.69 159.03,36.86 156.69,36.86 155.85,37.69 133.98,37.69 130.72,40.95 114.19,40.95 110.89,37.64 87.11,37.64 81.57,32.11 v1(31.75,32.11)
  BOTTOM w0.29: v1(31.75,32.11) 30.76,32.11 30.63,32.23 27.71,32.23 27.56,32.38 26.75,32.38 26.14,31.78 24.59,31.78 24.03,32.33 22.71,32.33 17.92,37.12 12.76,37.12 11.27,38.61 8.15,38.61 3.49,43.27 J19.S8
PS_EN_PSU_N: length 3.3
  TOP w0.29: R33.2 23.56,16.75 J21.1
SAS_BLAD1_RX1_N: length 36
  TOP w0.178: U1.A3 194.49,29.49 194.7,29.7 194.7,30.12 v1(194.26,30.56)
  BOTTOM w0.178: v1(194.26,30.56) 194.72,30.1 194.72,26.9 arc(194.71,26.84) 194.67,26.79 192.89,25.01 arc(192.7,24.73) 192.64,24.4 192.64,22.26 arc(192.63,22.2) 192.59,22.15 177.67,7.22 arc(177.62,7.19) 177.56,7.18 175.41,7.18 J25.E1
SAS_BLAD1_RX1_P: length 37.4
  TOP w0.178: v1(195.53,30.56) 195.05,30.09 195.05,29.74 195.3,29.49 U1.A2
  BOTTOM w0.178: v1(195.53,30.56) 195.07,30.1 195.07,26.9 arc(195.03,26.71) 194.92,26.54 193.14,24.76 arc(193.03,24.6) 192.99,24.4 192.99,22.26 arc(192.95,22.06) 192.84,21.9 189.02,18.08 189.02,17.83 188.64,17.46 188.4,17.46 188.01,17.07 188.01,16.83 187.63,16.45 187.39,16.45 187,16.06 187,15.82 186.63,15.44 186.38,15.44 186,15.05 186,14.81 185.62,14.43 185.37,14.43 184.99,14.04 184.99,13.8 184.61,13.42 184.37,13.42 183.75,12.81 183.75,12.57 183.37,12.19 183.13,12.19 177.92,6.97 arc(177.75,6.86) 177.56,6.82 175.41,6.82 J25.D1
SAS_BLAD1_RX2_N: length 36
  TOP w0.178: v1(191.87,31.68) 192.33,31.22 192.33,29.74 192.09,29.5 U1.A6
  IN2 w0.152: J25.I2 172.89,12.9 172.7,12.7 172.41,12.7 arc(172.27,12.73) 172.15,12.81 arc(172.07,12.93) 172.05,13.07 172.05,13.8 172.08,13.89 173.53,15.34 176.07,16.5 178.17,18.34 180.72,20.44 180.99,20.71 181.21,20.71 181.54,21.03 181.54,21.26 181.86,21.59 182.09,21.59 182.41,21.91 182.41,22.14 182.73,22.46 182.96,22.46 183.29,22.78 183.29,23.01 183.61,23.34 183.84,23.34 184.16,23.66 184.16,23.89 184.48,24.21 184.71,24.21 185.04,24.53 185.04,24.76 185.36,25.09 185.59,25.09 185.91,25.41 185.91,25.64 186.28,26.01 arc(186.35,26.09) 186.39,26.17 187.67,29.25 arc(187.7,29.34) 187.71,29.44 187.71,29.54 arc(187.71,29.57) 187.72,29.59 187.8,29.79 arc(187.82,29.83) 187.84,29.88 188.44,30.77 arc(188.47,30.81) 188.5,30.85 188.93,31.27 arc(188.97,31.31) 189.01,31.34 189.55,31.7 arc(189.59,31.73) 189.64,31.75 191.44,32.5 arc(191.54,32.53) 191.64,32.54 192.12,32.54 arc(192.16,32.53) 192.19,32.51 192.28,32.42 arc(192.3,32.39) 192.31,32.35 192.31,32.11 v1(191.87,31.68)
SAS_BLAD1_RX2_P: length 37.1
  TOP w0.178: U1.A5 192.89,29.5 192.68,29.71 192.68,31.22 v1(193.14,31.68)
  IN2 w0.152: v1(193.14,31.68) 192.71,32.11 192.71,32.35 arc(192.67,32.54) 192.56,32.71 192.48,32.79 arc(192.31,32.91) 192.12,32.94 191.64,32.94 arc(191.46,32.93) 191.29,32.87 189.48,32.12 arc(189.4,32.08) 189.32,32.04 188.78,31.67 arc(188.71,31.62) 188.64,31.56 188.22,31.13 arc(188.16,31.07) 188.1,30.99 187.51,30.1 arc(187.46,30.02) 187.42,29.94 187.34,29.75 arc(187.31,29.64) 187.3,29.54 187.3,29.44 arc(187.3,29.42) 187.29,29.4 186.02,26.33 arc(186.01,26.31) 186,26.3 180.45,20.75 arc(180.44,20.74) 180.44,20.74 177.91,18.65 arc(177.91,18.65) 177.9,18.65 177.9,18.64 175.84,16.84 173.29,15.68 171.74,14.12 171.64,13.89 171.64,13.07 arc(171.7,12.77) 171.87,12.52 arc(172.12,12.36) 172.41,12.3 172.69,12.3 172.89,12.1 J25.H2
SAS_BLAD1_RX3_N: length 37.5
  TOP w0.178: v1(189.46,30.59) 189.92,30.14 189.92,29.73 189.69,29.5 U1.A9
  BOTTOM w0.178: v1(189.46,30.59) 189.92,30.14 189.92,29.17 arc(189.91,29.11) 189.87,29.05 187.58,26.76 arc(187.58,26.76) 187.58,26.76 185.41,24.82 185.41,24.82 181.58,18.8 179.12,17.28 179.11,17.27 arc(179.11,17.27) 179.11,17.27 175.74,14.55 174.66,14.33 arc(174.46,14.29) 174.3,14.18 173.86,13.74 arc(173.75,13.58) 173.72,13.38 173.72,4.53 arc(173.7,4.47) 173.67,4.42 173.57,4.32 arc(173.52,4.29) 173.46,4.28 173.08,4.28 172.89,4.46 J25.C2
SAS_BLAD1_RX3_P: length 38.9
  TOP w0.178: U1.A8 190.49,29.5 190.27,29.73 190.27,30.14 v1(190.73,30.59)
  BOTTOM w0.178: v1(190.73,30.59) 190.27,30.14 190.27,29.17 arc(190.23,28.97) 190.12,28.81 189.73,28.42 189.73,28.17 189.36,27.8 189.11,27.8 188.73,27.41 188.73,27.17 188.35,26.79 188.1,26.79 187.83,26.52 arc(187.82,26.51) 187.81,26.5 185.68,24.59 184.99,23.5 184.98,23.5 185.03,23.26 184.75,22.81 184.51,22.76 184.51,22.75 184.22,22.3 184.22,22.29 184.27,22.06 183.98,21.61 183.75,21.55 183.75,21.55 183.46,21.09 183.45,21.09 183.51,20.85 183.22,20.4 182.98,20.35 182.98,20.34 182.69,19.88 182.69,19.89 182.74,19.65 182.46,19.2 182.22,19.14 182.22,19.14 181.84,18.54 179.32,16.99 175.9,14.23 174.69,13.98 174.66,13.98 arc(174.6,13.96) 174.55,13.93 174.11,13.5 arc(174.08,13.44) 174.07,13.38 174.07,4.53 arc(174.03,4.33) 173.92,4.17 173.82,4.07 arc(173.66,3.96) 173.46,3.92 173.14,3.92 172.89,3.68 J25.B2
SAS_BLAD1_RX4_N: length 36.1
  TOP w0.178: v1(185.5,29.31) 185.04,29.77 185.04,30 185.29,30.25 187.3,30.25 187.54,30.01 187.54,29.75 187.3,29.5 U1.A12
  IN2 w0.152: J25.E3 170.89,7.36 170.74,7.2 170.33,7.2 arc(170.24,7.22) 170.17,7.27 170.14,7.3 arc(170.11,7.35) 170.1,7.4 170.1,13.26 170.22,14.01 170.63,15.01 172.85,17.22 arc(173.02,17.33) 173.21,17.37 173.71,17.37 arc(173.8,17.38) 173.9,17.41 174.48,17.65 arc(174.53,17.67) 174.57,17.7 175.65,18.42 arc(175.69,18.45) 175.73,18.48 178.11,20.87 178.35,20.87 178.68,21.2 178.68,21.43 179,21.76 179.24,21.76 179.56,22.08 179.56,22.32 182.23,24.99 arc(182.43,25.29) 182.5,25.64 182.5,26.33 arc(182.54,26.53) 182.65,26.69 183.65,27.69 arc(183.81,27.8) 184,27.84 184.4,27.84 arc(184.59,27.88) 184.76,27.99 184.92,28.15 arc(185.03,28.31) 185.07,28.51 185.07,28.88 v1(185.5,29.31)
SAS_BLAD1_RX4_P: length 37.7
  TOP w0.178: U1.A11 188.09,29.5 187.9,29.7 187.9,30.15 187.44,30.6 185.15,30.6 184.69,30.14 184.69,29.77 v1(184.23,29.31)
  IN2 w0.152: J25.D3 170.89,6.66 170.76,6.8 170.33,6.8 arc(170.09,6.85) 169.88,6.98 169.86,7.01 arc(169.73,7.19) 169.69,7.4 169.69,13.29 169.83,14.13 170.29,15.24 172.56,17.51 arc(172.86,17.71) 173.21,17.78 173.71,17.78 arc(173.73,17.78) 173.74,17.79 174.33,18.03 arc(174.33,18.03) 174.34,18.04 175.42,18.76 arc(175.43,18.76) 175.44,18.77 181.94,25.28 arc(182.05,25.44) 182.09,25.64 182.09,26.33 arc(182.16,26.68) 182.36,26.98 183.36,27.98 arc(183.65,28.18) 184,28.24 184.4,28.24 arc(184.44,28.25) 184.47,28.27 184.63,28.44 arc(184.65,28.47) 184.66,28.51 184.66,28.88 v1(184.23,29.31)
SAS_BLAD1_RX5_N: length 28.9
  TOP w0.178: v1(175.25,31) 175.71,30.54 175.71,29.73 175.49,29.5 U3.A3
  IN2 w0.152: v1(175.25,31) 175.68,31.43 175.68,31.75 arc(175.67,31.79) 175.65,31.82 175.48,32 arc(175.44,32.02) 175.41,32.03 175.09,32.03 arc(175.05,32.02) 175.02,32 174.78,31.77 174.44,31.42 173.85,30.83 173.84,30.83 arc(173.82,30.79) 173.81,30.75 173.81,29.85 173.99,29.67 173.99,29.26 173.81,29.09 173.81,28.63 173.99,28.45 173.99,28.05 173.81,27.87 173.81,27.28 173.96,27.13 173.96,26.67 173.81,26.52 173.81,26.14 arc(173.85,25.95) 173.96,25.78 174.04,25.7 arc(174.15,25.54) 174.19,25.34 174.19,23.43 arc(174.15,23.23) 174.04,23.07 173.85,22.87 173.85,22.64 173.52,22.32 173.3,22.32 172.97,22 172.97,21.77 172.65,21.44 172.42,21.44 172.1,21.12 172.1,20.89 171.77,20.57 171.55,20.57 170.86,19.88 arc(170.75,19.72) 170.71,19.53 170.71,17.71 arc(170.67,17.52) 170.56,17.35 168.2,14.98 arc(168.09,14.82) 168.05,14.62 168.05,13.09 arc(168.08,12.94) 168.16,12.82 168.16,12.82 arc(168.28,12.73) 168.43,12.7 168.74,12.7 168.89,12.86 J25.I4
SAS_BLAD1_RX5_P: length 30
  TOP w0.178: U3.A2 176.29,29.5 176.06,29.73 176.06,30.54 v1(176.52,31)
  IN2 w0.152: J25.H4 168.89,12.11 168.7,12.3 168.43,12.3 arc(168.13,12.36) 167.87,12.53 arc(167.7,12.79) 167.64,13.09 167.64,14.62 arc(167.71,14.97) 167.91,15.27 170.28,17.64 arc(170.3,17.67) 170.31,17.71 170.31,19.53 arc(170.38,19.88) 170.57,20.17 173.76,23.35 arc(173.78,23.39) 173.79,23.43 173.79,25.34 arc(173.78,25.38) 173.76,25.41 173.67,25.5 arc(173.48,25.79) 173.41,26.14 173.41,30.75 arc(173.45,30.95) 173.56,31.12 174.15,31.71 174.73,32.29 arc(174.89,32.4) 175.09,32.44 175.41,32.44 arc(175.6,32.4) 175.76,32.29 175.94,32.11 arc(176.05,31.95) 176.09,31.75 176.09,31.43 v1(176.52,31)
SAS_BLAD1_RX6_N: length 34.2
  TOP w0.178: v1(172.88,32.92) 173.31,32.48 173.31,29.73 173.08,29.5 U3.A6
  BOTTOM w0.178: v1(172.88,32.92) 173.34,32.46 173.34,27.43 arc(173.4,27.1) 173.59,26.83 173.67,26.74 arc(173.7,26.69) 173.72,26.63 173.72,22.38 arc(173.72,22.37) 173.71,22.36 arc(173.71,22.34) 173.7,22.32 173.44,21.68 arc(173.42,21.65) 173.4,21.63 168.76,16.98 arc(168.73,16.95) 168.72,16.92 168.01,15.2 arc(168,15.19) 168,15.17 167.83,14.46 167.73,14.05 167.72,13.97 167.72,7.37 arc(167.71,7.3) 167.66,7.23 167.66,7.23 arc(167.6,7.19) 167.53,7.18 167.07,7.18 166.89,7.36 J25.E5
SAS_BLAD1_RX6_P: length 35.6
  TOP w0.178: v1(174.15,32.92) 173.66,32.43 173.66,29.73 173.89,29.5 U3.A5
  BOTTOM w0.178: J25.D5 166.89,6.63 167.08,6.82 167.53,6.82 arc(167.74,6.86) 167.91,6.98 167.91,6.98 arc(168.03,7.16) 168.07,7.37 168.07,13.97 168.34,15.08 169.03,16.76 172.71,20.44 172.96,20.44 173.33,20.82 173.33,21.06 173.54,21.26 173.65,21.38 arc(173.72,21.46) 173.76,21.54 174.03,22.18 174.06,22.33 arc(174.07,22.35) 174.07,22.38 174.07,22.49 174.24,22.66 174.24,23.2 174.07,23.37 174.07,23.92 174.24,24.09 174.24,24.62 174.07,24.8 174.07,25.34 174.24,25.52 174.24,26.05 174.07,26.22 174.07,26.63 arc(174.03,26.83) 173.92,26.99 173.83,27.07 arc(173.72,27.24) 173.69,27.43 173.69,27.79 173.86,27.97 173.86,28.5 173.69,28.67 173.69,30.59 173.86,30.76 173.86,31.3 173.69,31.47 173.69,32.46 v1(174.15,32.92)
SAS_BLAD1_RX7_N: length 33.9
  TOP w0.178: U3.A9 170.68,29.5 170.91,29.73 170.91,31.53 v1(170.45,31.99)
  IN2 w0.152: v1(170.45,31.99) 170.88,32.42 170.88,32.77 arc(170.87,32.81) 170.85,32.84 170.73,32.96 arc(170.69,32.99) 170.66,32.99 169.25,32.99 arc(169.05,32.96) 168.89,32.85 166.65,30.6 arc(166.54,30.44) 166.5,30.24 166.5,28.76 arc(166.54,28.57) 166.65,28.4 169.29,25.75 arc(169.4,25.59) 169.44,25.39 169.44,22.74 arc(169.37,22.39) 169.18,22.09 168.95,21.87 168.95,21.74 168.95,21.61 168.63,21.29 168.37,21.29 168.04,20.96 168.04,20.83 168.04,20.7 167.72,20.38 167.46,20.38 166.36,19.28 166.36,19.15 166.36,19.02 166.04,18.7 165.78,18.7 165.45,18.37 165.45,18.24 165.45,18.11 165.13,17.79 164.87,17.79 164.54,17.46 164.54,17.33 164.54,17.2 164.22,16.88 163.96,16.88 163.75,16.67 arc(163.64,16.5) 163.6,16.31 163.6,13.04 arc(163.63,12.91) 163.7,12.8 arc(163.81,12.73) 163.94,12.7 164.7,12.7 164.89,12.9 J25.I6
SAS_BLAD1_RX7_P: length 35.1
  TOP w0.178: U3.A8 171.49,29.5 171.26,29.73 171.26,31.53 v1(171.72,31.99)
  IN2 w0.152: v1(171.72,31.99) 171.29,32.42 171.29,32.77 arc(171.25,32.96) 171.14,33.13 171.01,33.25 arc(170.85,33.36) 170.66,33.4 169.25,33.4 arc(168.9,33.33) 168.6,33.13 166.36,30.89 arc(166.16,30.59) 166.09,30.24 166.09,28.76 arc(166.16,28.41) 166.36,28.11 169.01,25.46 arc(169.03,25.43) 169.04,25.39 169.04,22.74 arc(169,22.55) 168.89,22.38 163.46,16.96 arc(163.26,16.66) 163.19,16.31 163.19,13.04 arc(163.25,12.76) 163.41,12.52 arc(163.66,12.35) 163.94,12.3 164.72,12.3 164.89,12.12 J25.H6
SAS_BLAD1_RX8_N: length 35.5
  TOP w0.178: U3.A12 168.29,29.5 168.51,29.73 168.51,30.27 v1(168.05,30.73)
  BOTTOM w0.178: v1(168.05,30.73) 168.51,31.19 168.51,31.51 arc(168.5,31.57) 168.46,31.62 168.46,31.63 arc(168.4,31.67) 168.34,31.68 167.75,31.68 arc(167.56,31.64) 167.39,31.53 166.39,30.52 arc(166.28,30.36) 166.24,30.16 166.24,27.21 arc(166.2,27.01) 166.09,26.85 163.47,24.22 arc(163.36,24.06) 163.32,23.86 163.32,23.14 163.49,22.97 163.49,22.44 163.32,22.26 163.32,21.73 163.49,21.56 163.49,21.02 163.32,20.85 163.32,4.94 arc(163.36,4.75) 163.47,4.58 163.62,4.42 arc(163.79,4.31) 163.98,4.28 164.37,4.28 J25.C6
SAS_BLAD1_RX8_P: length 36.8
  TOP w0.178: v1(169.32,30.73) 168.86,30.27 168.86,29.73 169.09,29.5 U3.A11
  BOTTOM w0.178: J25.B6 164.37,3.92 163.98,3.92 arc(163.65,3.99) 163.37,4.18 163.22,4.33 arc(163.03,4.61) 162.97,4.94 162.97,23.86 arc(163.03,24.19) 163.22,24.47 165.84,27.09 arc(165.88,27.15) 165.89,27.21 165.89,30.16 arc(165.95,30.49) 166.14,30.77 167.15,31.78 arc(167.43,31.96) 167.75,32.03 168.34,32.03 arc(168.54,31.99) 168.7,31.88 168.71,31.87 arc(168.82,31.71) 168.86,31.51 168.86,31.19 v1(169.32,30.73)
SAS_BLAD1_TX1_N: length 39.6
  TOP w0.178: U1.B3 194.89,24.81 195.12,24.58 195.12,24.26 195.53,23.85 197.21,23.85 v1(197.66,23.4)
  IN2 w0.152: J25.B1 175.39,3 177.82,3 arc(177.92,3.01) 178.01,3.04 185.36,6.09 arc(185.37,6.1) 185.39,6.11 arc(185.4,6.11) 185.41,6.12 arc(185.44,6.14) 185.46,6.16 192.77,13.47 192.78,13.48 198.14,21.51 arc(198.15,21.52) 198.15,21.53 198.72,22.9 arc(198.73,22.92) 198.73,22.94 198.73,23.52 arc(198.71,23.64) 198.64,23.74 arc(198.53,23.81) 198.41,23.83 198.09,23.83 v1(197.66,23.4)
SAS_BLAD1_TX1_P: length 41.1
  TOP w0.178: v1(197.66,24.67) 197.19,24.2 195.68,24.2 195.47,24.41 195.47,24.58 195.69,24.81 U1.B2
  IN2 w0.152: v1(197.66,24.67) 198.09,24.24 198.41,24.24 arc(198.69,24.18) 198.92,24.03 arc(199.08,23.79) 199.14,23.52 199.14,22.94 arc(199.13,22.84) 199.1,22.75 198.53,21.37 arc(198.51,21.33) 198.48,21.28 198.48,21.28 193.11,13.25 193.09,13.21 192.05,12.18 192.05,11.94 191.73,11.62 191.49,11.62 191.17,11.3 191.17,11.06 190.85,10.73 190.61,10.73 190.28,10.41 190.28,10.17 189.96,9.85 189.72,9.85 189.4,9.53 189.4,9.29 189.08,8.96 188.84,8.96 188.51,8.64 188.51,8.4 188.19,8.08 187.95,8.08 187.63,7.76 187.63,7.52 187.31,7.2 187.07,7.2 185.74,5.87 arc(185.69,5.83) 185.64,5.78 arc(185.61,5.77) 185.58,5.75 arc(185.55,5.73) 185.52,5.72 178.17,2.66 arc(177.99,2.61) 177.82,2.59 175.38,2.59 J25.A1
SAS_BLAD1_TX2_N: length 29.4
  TOP w0.178: U1.B6 192.49,24.99 192.72,24.76 192.72,18.98 v1(192.26,18.52)
  IN2 w0.152: J25.H1 175.39,11.4 186.48,11.4 arc(186.67,11.44) 186.84,11.55 192.54,17.26 arc(192.65,17.42) 192.69,17.62 192.69,18.08 v1(192.26,18.52)
SAS_BLAD1_TX2_P: length 30.5
  TOP w0.178: U1.B5 193.3,24.99 193.07,24.76 193.07,18.98 v1(193.53,18.52)
  IN2 w0.152: J25.G1 175.39,11 179.03,11 179.2,10.82 179.66,10.82 179.84,11 180.3,11 180.47,10.82 180.93,10.82 181.1,11 181.56,11 181.74,10.82 182.2,10.82 182.37,11 186.48,11 arc(186.83,11.07) 187.13,11.26 192.83,16.97 arc(193.03,17.27) 193.1,17.62 193.1,18.08 v1(193.53,18.52)
SAS_BLAD1_TX3_N: length 30.3
  TOP w0.178: U1.B9 190.09,24.81 190.32,24.58 190.32,24.04 v1(189.86,23.58)
  IN2 w0.152: v1(189.86,23.58) 190.29,23.15 190.29,22.53 arc(190.25,22.34) 190.14,22.17 182.5,14.53 arc(182.33,14.42) 182.14,14.38 174.78,14.38 arc(174.43,14.31) 174.14,14.11 173.96,13.93 arc(173.76,13.63) 173.69,13.28 173.69,8.7 arc(173.68,8.62) 173.63,8.56 arc(173.57,8.52) 173.5,8.5 173.12,8.5 172.89,8.73 J25.F2
SAS_BLAD1_TX3_P: length 31.6
  TOP w0.178: U1.B8 190.89,24.81 190.67,24.58 190.67,24.04 v1(191.13,23.58)
  IN2 w0.152: v1(191.13,23.58) 190.7,23.15 190.7,22.53 arc(190.63,22.18) 190.43,21.89 182.78,14.24 arc(182.49,14.04) 182.14,13.97 181.74,13.97 181.59,13.82 181.13,13.82 180.98,13.97 180.52,13.97 180.37,13.82 179.91,13.82 179.76,13.97 179.3,13.97 179.15,13.82 178.69,13.82 178.54,13.97 178.08,13.97 177.93,13.82 177.47,13.82 177.32,13.97 176.86,13.97 176.71,13.82 176.25,13.82 176.1,13.97 174.78,13.97 arc(174.59,13.93) 174.43,13.82 174.25,13.64 arc(174.14,13.48) 174.1,13.28 174.1,8.7 arc(174.05,8.47) 173.92,8.27 arc(173.73,8.14) 173.5,8.1 173.09,8.1 172.89,7.89 J25.E2
SAS_BLAD1_TX4_N: length 34.3
  TOP w0.178: v1(185.27,26.82) 184.81,26.37 184.81,25.08 186.15,23.74 187.56,23.74 187.92,24.1 187.92,24.58 187.69,24.81 U1.B12
  BOTTOM w0.178: J25.H3 170.89,11.56 171.08,11.38 171.53,11.38 arc(171.6,11.39) 171.66,11.43 arc(171.7,11.49) 171.71,11.56 171.71,13.98 171.95,14.56 173.39,16 arc(173.67,16.19) 174,16.25 174.26,16.25 arc(174.28,16.25) 174.29,16.26 175.11,16.6 arc(175.14,16.61) 175.16,16.63 177.71,19.18 arc(177.99,19.37) 178.32,19.43 178.6,19.43 arc(178.62,19.43) 178.64,19.44 179.42,19.76 arc(179.45,19.78) 179.47,19.8 180.62,20.95 arc(180.64,20.97) 180.66,21 181.6,23.28 arc(181.61,23.31) 181.62,23.34 181.62,26.54 arc(181.68,26.86) 181.87,27.14 182.77,28.04 arc(183.05,28.23) 183.37,28.3 184.09,28.3 arc(184.29,28.26) 184.45,28.15 184.66,27.94 arc(184.77,27.77) 184.81,27.58 184.81,27.28 v1(185.27,26.82)
SAS_BLAD1_TX4_P: length 35.4
  TOP w0.178: U1.B11 188.49,24.81 188.27,24.58 188.27,23.96 187.71,23.39 186,23.39 184.46,24.94 184.46,26.36 v1(184,26.82)
  BOTTOM w0.178: v1(184,26.82) 184.46,27.28 184.46,27.58 arc(184.45,27.64) 184.41,27.69 184.2,27.9 arc(184.15,27.93) 184.09,27.95 183.37,27.95 arc(183.18,27.91) 183.02,27.8 182.11,26.9 arc(182,26.73) 181.97,26.54 181.97,26.22 182.14,26.04 182.14,25.51 181.97,25.34 181.97,24.79 182.14,24.62 182.14,24.09 181.97,23.91 181.97,23.34 arc(181.96,23.24) 181.93,23.15 180.98,20.86 arc(180.93,20.78) 180.87,20.7 179.72,19.55 arc(179.64,19.48) 179.56,19.44 178.78,19.11 arc(178.69,19.09) 178.6,19.08 178.32,19.08 arc(178.13,19.04) 177.96,18.93 177.64,18.61 177.64,18.4 177.27,18.02 177.05,18.02 175.41,16.38 arc(175.34,16.32) 175.25,16.27 174.43,15.93 arc(174.35,15.91) 174.26,15.9 174,15.9 arc(173.8,15.86) 173.64,15.75 172.25,14.36 172.06,13.91 172.06,11.55 arc(172.02,11.35) 171.91,11.18 arc(171.73,11.07) 171.53,11.02 171,11.02 170.89,10.92 J25.G3
SAS_BLAD1_TX5_N: length 26.8
  TOP w0.178: U3.B3 175.89,24.81 176.11,24.58 176.11,24.26 176.54,23.83 177.79,23.83 v1(178.22,23.39)
  BOTTOM w0.178: J25.F4 168.89,8.66 169.08,8.48 169.52,8.48 arc(169.59,8.49) 169.66,8.53 arc(169.7,8.59) 169.71,8.66 169.71,13.89 169.72,13.98 169.9,14.7 169.91,14.75 arc(169.91,14.76) 169.92,14.77 170.31,15.72 arc(170.33,15.75) 170.35,15.78 172.5,17.93 arc(172.75,18.1) 173.05,18.16 arc(173.08,18.16) 173.11,18.18 176.16,21.24 arc(176.33,21.35) 176.52,21.39 177.84,21.39 arc(178.04,21.43) 178.2,21.54 179.1,22.44 arc(179.21,22.6) 179.25,22.8 179.25,23.59 arc(179.24,23.65) 179.21,23.7 179.1,23.81 arc(179.05,23.84) 178.99,23.85 178.68,23.85 v1(178.22,23.39)
SAS_BLAD1_TX5_P: length 28
  TOP w0.178: U3.B2 176.68,24.81 176.46,24.58 176.46,24.41 176.69,24.18 177.74,24.18 v1(178.22,24.66)
  BOTTOM w0.178: v1(178.22,24.66) 178.68,24.2 178.99,24.2 arc(179.18,24.16) 179.35,24.05 179.45,23.95 arc(179.56,23.78) 179.6,23.59 179.6,22.8 arc(179.54,22.47) 179.35,22.19 179.19,22.02 179.19,21.78 178.81,21.4 178.57,21.4 178.45,21.29 arc(178.17,21.1) 177.84,21.04 177.64,21.04 177.47,20.86 176.93,20.86 176.76,21.04 176.52,21.04 arc(176.46,21.02) 176.41,20.99 176.16,20.73 176.16,20.49 175.78,20.11 175.53,20.11 175.53,20.11 175.15,19.72 175.15,19.48 174.77,19.1 174.53,19.1 174.14,18.72 174.14,18.47 173.76,18.09 173.52,18.09 173.35,17.93 arc(173.21,17.84) 173.05,17.81 arc(172.89,17.77) 172.75,17.68 170.62,15.55 170.25,14.65 170.06,13.89 170.06,8.66 arc(170.02,8.46) 169.9,8.28 arc(169.73,8.17) 169.52,8.12 169.1,8.12 168.89,7.91 J25.E4
SAS_BLAD1_TX6_N: length 32.2
  TOP w0.178: v1(168.73,18.52) 168.22,18.01 168.22,17.83 168.45,17.6 171.23,17.6 arc(171.46,17.75) 171.72,17.8 172.97,17.8 arc(173.03,17.81) 173.08,17.85 173.71,18.48 arc(173.75,18.53) 173.76,18.59 173.76,24.53 173.49,24.81 U3.B6
  IN2 w0.152: v1(168.73,18.52) 168.3,18.08 168.3,18.08 arc(168.3,18.04) 168.3,18 arc(168.26,17.76) 168.12,17.56 166.12,15.56 arc(166.1,15.52) 166.09,15.48 166.09,15.15 166.27,14.97 166.27,14.51 166.09,14.33 166.09,3.26 arc(166.11,3.16) 166.16,3.08 arc(166.25,3.02) 166.34,3 166.78,3 166.89,3.11 J25.B5
SAS_BLAD1_TX6_P: length 33.7
  TOP w0.178: U3.B5 174.29,24.81 174.11,24.63 174.11,18.59 arc(174.07,18.4) 173.96,18.23 173.33,17.6 arc(173.16,17.49) 172.97,17.45 171.72,17.45 arc(171.59,17.42) 171.48,17.35 arc(171.37,17.28) 171.24,17.25 168.3,17.25 167.87,17.68 167.87,18.11 v1(167.46,18.52)
  IN2 w0.152: J25.A5 166.89,2.48 166.77,2.6 166.34,2.6 arc(166.09,2.65) 165.88,2.79 arc(165.73,3) 165.68,3.26 165.68,15.48 arc(165.72,15.68) 165.83,15.84 167.83,17.85 arc(167.9,18) 167.83,18.15 v1(167.46,18.52)
SAS_BLAD1_TX7_N: length 22.7
  TOP w0.178: v1(170.85,23.7) 171.34,24.18 171.34,24.61 171.09,24.86 U3.B9
  BOTTOM w0.178: J25.H5 166.89,11.49 166.77,11.38 166.25,11.38 arc(166.18,11.39) 166.12,11.43 arc(166.08,11.49) 166.07,11.56 166.07,17 166.24,17.17 166.24,17.7 166.07,17.87 166.07,18.41 166.24,18.58 166.24,19.11 166.07,19.29 166.07,19.82 166.24,19.99 166.24,20.53 166.07,20.7 166.07,20.95 arc(166.1,21.14) 166.21,21.31 169.25,24.34 arc(169.36,24.5) 169.39,24.69 arc(169.43,24.88) 169.54,25.04 169.78,25.28 arc(169.95,25.39) 170.14,25.43 170.73,25.43 arc(170.79,25.42) 170.84,25.38 171.2,25.03 171.31,24.8 171.31,24.16 v1(170.85,23.7)
